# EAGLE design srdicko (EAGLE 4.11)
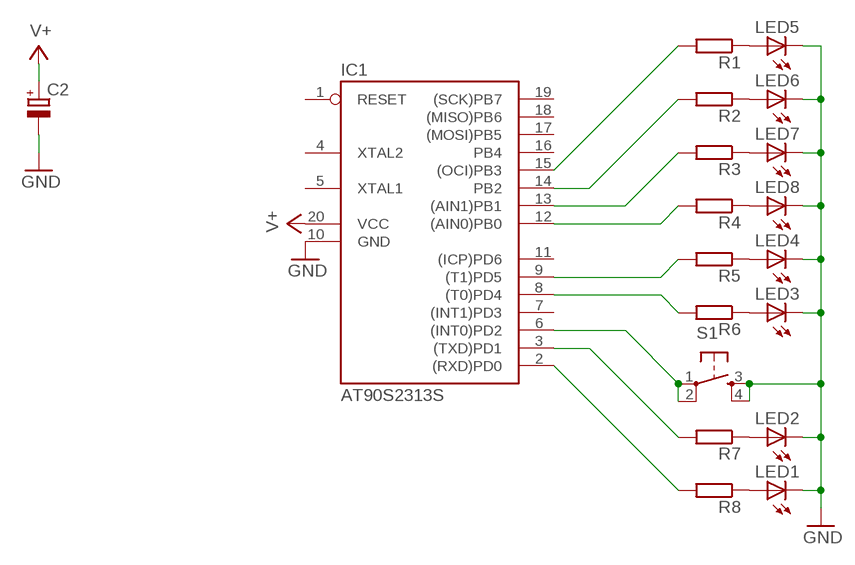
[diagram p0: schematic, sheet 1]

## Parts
C2  CPOL-EUE22-6AXIAL  [E22-6]
IC1  AT90S2313S  [SO20W]
LED1  LEDCHIPLED_1206  [CHIPLED_1206]
LED2  LEDCHIPLED_1206  [CHIPLED_1206]
LED3  LEDCHIPLED_1206  [CHIPLED_1206]
LED4  LEDCHIPLED_1206  [CHIPLED_1206]
LED5  LEDCHIPLED_1206  [CHIPLED_1206]
LED6  LEDCHIPLED_1206  [CHIPLED_1206]
LED7  LEDCHIPLED_1206  [CHIPLED_1206]
LED8  LEDCHIPLED_1206  [CHIPLED_1206]
R1  R-EU_M1206  [M1206]
R2  R-EU_M1206  [M1206]
R3  R-EU_M1206  [M1206]
R4  R-EU_M1206  [M1206]
R5  R-EU_M1206  [M1206]
R6  R-EU_M1206  [M1206]
R7  R-EU_M1206  [M1206]
R8  R-EU_M1206  [M1206]
S1  TAC_SWITCHSND  [TACTILE_SWITCH_SMD]

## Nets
N$1: LED5.A R1.1
N$2: LED6.A R2.1
N$3: LED7.A R3.1
N$4: LED8.A R4.1
N$5: LED4.A R5.1
N$6: LED3.A R6.1
N$7: LED2.A R7.1
N$8: IC1.3((TXD)PD1) R7.2
N$9: LED1.A R8.1
N$10: IC1.2((RXD)PD0) R8.2
N$11: IC1.8((T0)PD4) R6.2
N$12: IC1.9((T1)PD5) R5.2
N$13: IC1.12((AIN0)PB0) R4.2
N$14: IC1.13((AIN1)PB1) R3.2
N$15: IC1.14(PB2) R2.2
N$16: IC1.15((OCI)PB3) R1.2
N$17: IC1.6((INT0)PD2) S1.1 S1.2
N$19: C2.- IC1.10(GND) LED1.C LED2.C LED3.C LED4.C LED5.C LED6.C LED7.C LED8.C S1.3 S1.4 ; supply symbol labelled GND
V+: C2.+ IC1.20(VCC)
Unconnected: IC1.1(RESET) IC1.4(XTAL2) IC1.5(XTAL1) IC1.7((INT1)PD3) IC1.11((ICP)PD6) IC1.16(PB4) IC1.17((MOSI)PB5) IC1.18((MISO)PB6) IC1.19((SCK)PB7)

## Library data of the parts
C2 = rcl:CPOL-EU: POLARIZED CAPACITOR, European symbol
IC1 = atmel:AT90S2313: MICROCONTROLLER 2 Kbytes FLASH 128 bytes SRAM 128 bytes EEPROM UART
LED1-LED8 = led:LED: LED
R1-R8 = rcl:R-EU_: RESISTOR, European symbol
S1 = SparkFun:TAC_SWITCH: Momentary Switch Button commonly used for reset or general input. Spark Fun Electronics SKU : COM-00097

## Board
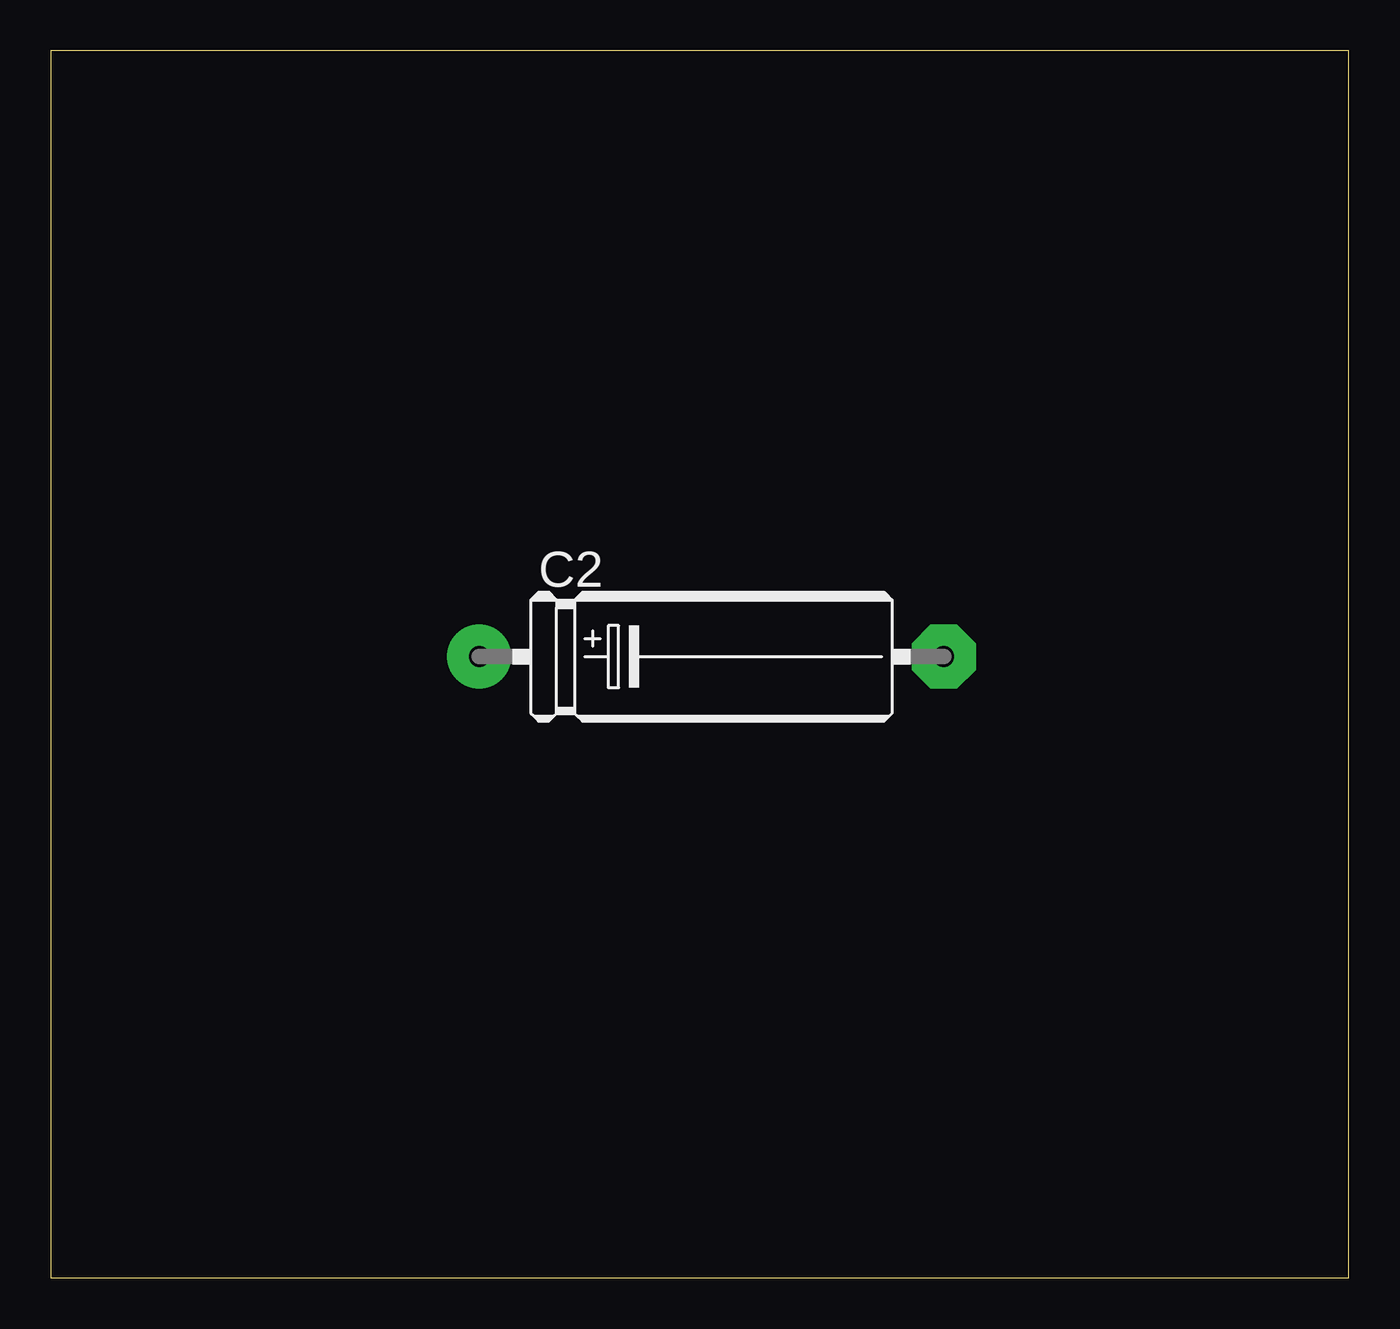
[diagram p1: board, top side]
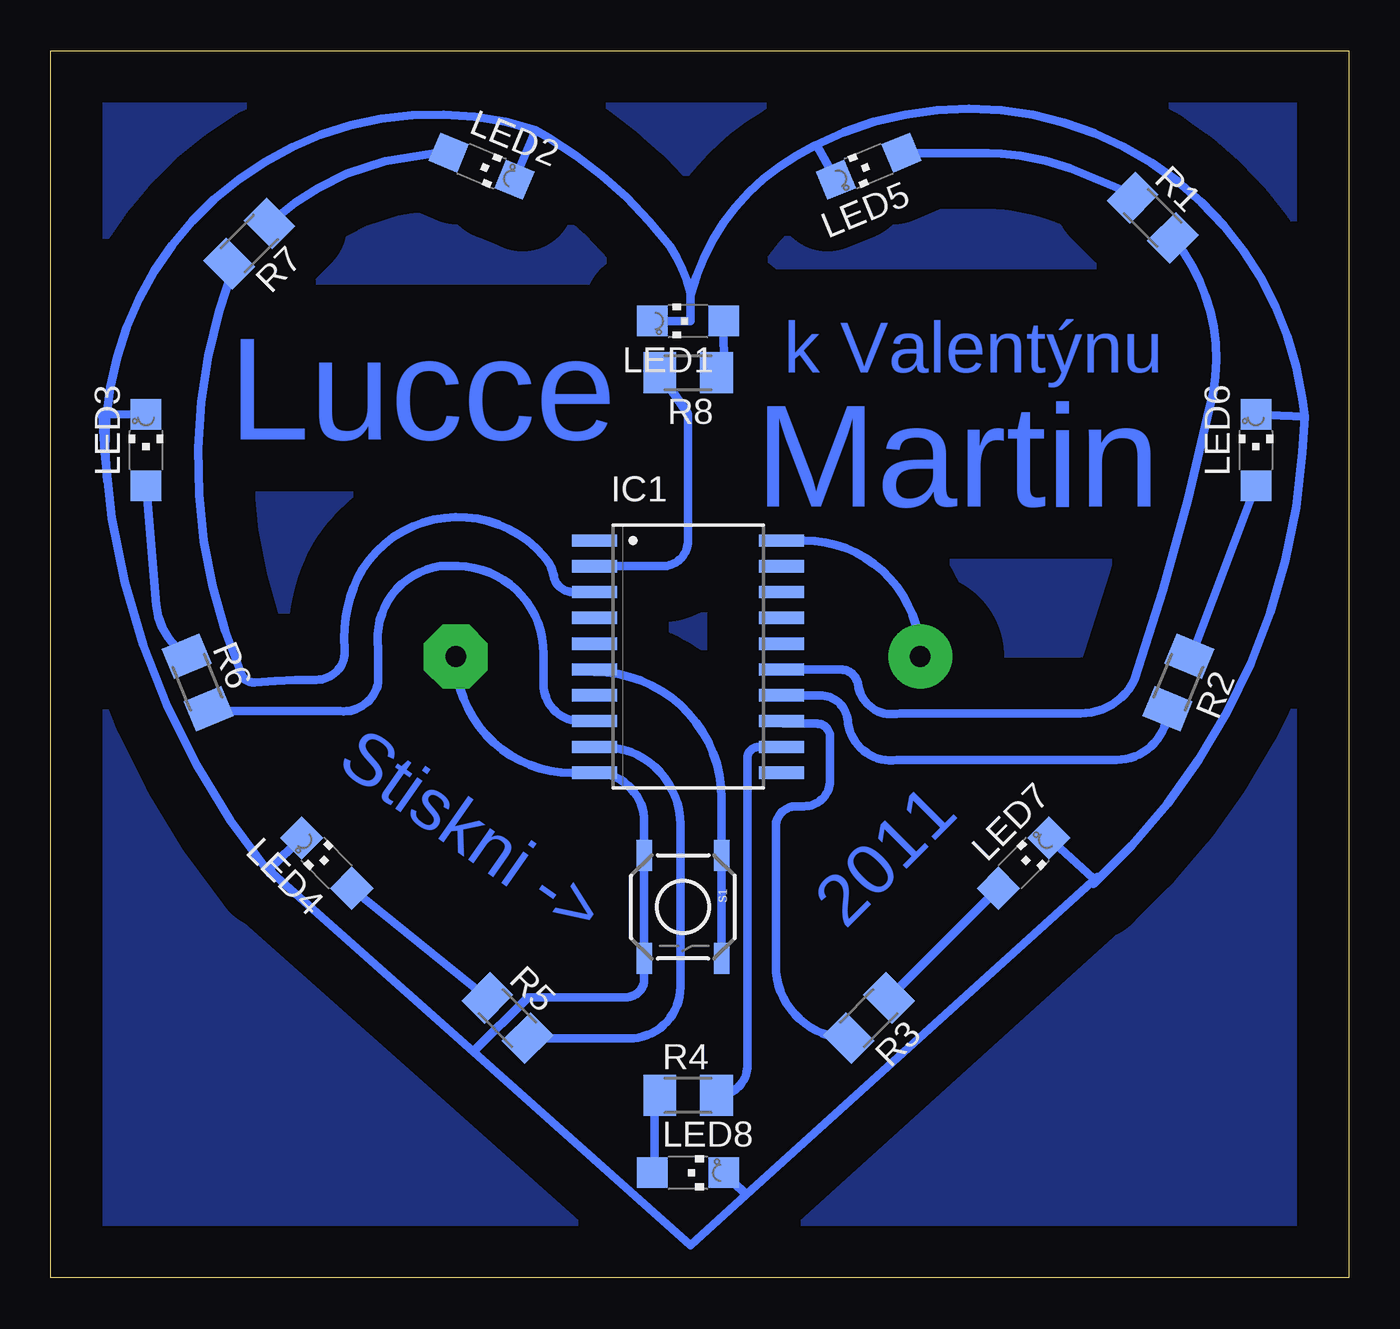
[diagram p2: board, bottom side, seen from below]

Size 63.86 x 60.38 mm. Coordinates in mm from the lower left corner, seen from the top.
Outline: 0,0 63.86,0 63.86,60.38 0,60.38 0,0
Copper layers (1*16): Top 0.035mm / dielectric 1.5mm / Bottom 0.035mm
Design rules "default": minimum track width 10mil, minimum drill 24mil, track to track 8mil, track to pad 8mil, pad to pad 8mil, via to via 8mil, smd to smd 8mil, copper to edge 40mil, drill to drill 8mil, minimum pad ring 10mil, minimum via ring 8mil, stop-mask expansion 4mil, vias tented up to drill 0mil, thermal gap 10mil

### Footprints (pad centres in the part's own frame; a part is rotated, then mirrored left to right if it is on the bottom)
E22-6 = drill 1.016 pad 3.15 round: + -11.43,0 | drill 1.016 pad 3.15 octagon: - 11.43,0
SO20W = smd 0.6 x 2.2: 1 -5.715,-4.6; 2 -4.445,-4.6; 3 -3.175,-4.6; 4 -1.905,-4.6; 5 -0.635,-4.6; 6 0.635,-4.6; 7 1.905,-4.6; 8 3.175,-4.6; 9 4.445,-4.6; 10 5.715,-4.6; 11 5.715,4.6; 12 4.445,4.6; 13 3.175,4.6; 14 1.905,4.6; 15 0.635,4.6; 16 -0.635,4.6; 17 -1.905,4.6; 18 -3.175,4.6; 19 -4.445,4.6; 20 -5.715,4.6
CHIPLED_1206 = smd 1.5 x 1.5: A 0,-1.75; C 0,1.75
M1206 = smd 1.6 x 2: 1 -1.4,0; 2 1.4,0
TACTILE_SWITCH_SMD = smd 1.524 x 0.762: 1 -2.54,1.905; 2 2.54,1.905; 3 -2.54,-1.905; 4 2.54,-1.905

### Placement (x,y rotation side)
C2  32.51,30.57 0 top
IC1  32.51,30.57 270 bottom
LED1  32.51,47.08 90 bottom
LED2  42.67,54.7 247.5 bottom
LED3  59.18,40.73 0 bottom
LED4  50.29,20.41 45 bottom
LED5  23.62,54.7 112.5 bottom
LED6  4.57,40.73 0 bottom
LED7  16,20.41 315 bottom
LED8  32.51,5.17 270 bottom
R1  9.65,52.16 315 bottom
R2  8.38,29.3 247.5 bottom
R3  23.62,12.79 225 bottom
R4  32.51,8.98 0 bottom
R5  41.4,12.79 315 bottom
R6  56.64,29.3 292.5 bottom
R7  54.1,50.89 225 bottom
R8  32.51,44.54 180 bottom
S1  32.76,18.25 270 bottom

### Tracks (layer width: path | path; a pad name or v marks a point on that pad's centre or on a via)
N$1
  Bottom 0.406: 22.04,55.33 22.22,55.33 | 22.04,55.33 LED5.A | R1.1 10.93,53.44 13.72,54.6 14.93,54.97 16.15,55.21 17.1,55.3 17.73,55.33 22.04,55.33
N$2
  Bottom 0.406: R2.1 7.74,30.57 LED6.A
N$3
  Bottom 0.406: R3.1 LED7.A
N$4
  Bottom 0.406: LED8.A 34.16,5.27 34.16,8.73 R4.1
N$5
  Bottom 0.406: R5.1 42.41,13.81 LED4.A
N$6
  Bottom 0.406: LED3.A 58.67,33.11 arc-50 57.27,30.7 R6.1
N$7
  Bottom 0.406: R7.1 51.83,52.9 50.7,53.63 49.31,54.33 47.4,54.95 44.49,55.4 LED2.A
N$8
  Bottom 0.406: IC1.3 38.1,33.74 arc83 39.11,34.51 arc-33 39.62,35.52 arc-106 48.51,34.89 arc-36 49.4,30.95 arc96 50.8,29.43 arc-5 53.84,29.3 arc72 54.48,29.68 arc44 54.86,49.75 R7.2
N$9
  Bottom 0.406: R8.1 30.73,44.54 LED1.A
N$10
  Bottom 0.406: R8.2 32.51,42.51 32.51,36.28 arc90 33.78,35.01 IC1.2
N$11
  Bottom 0.406: IC1.8 37.59,27.39 arc90 39.62,29.04 39.62,30.7 arc-90 43.81,35.01 44.7,35.01 arc-90 47.75,30.95 47.75,29.3 arc90 49.78,27.9 55.88,27.9 arc90 56,28.03 arc90 56.03,28 R6.2
N$12
  Bottom 0.406: IC1.9 36.7,26.12 arc90 32.89,22.31 32.89,14.31 arc90 35.43,11.77 40.51,11.77 arc90 40.48,11.8 R5.2
N$13
  Bottom 0.406: IC1.12 28.95,26.12 arc-90 29.59,25.62 29.59,10.5 arc90 30.98,8.98 R4.2
N$14
  Bottom 0.406: R3.2 arc90 28.19,15.38 28.19,22.19 arc90 27.17,23.2 26.79,23.2 arc-90 25.52,24.47 25.52,26.63 arc-90 26.16,27.27 27.81,27.27 27.81,27.29 arc-90 IC1.13
N$15
  Bottom 0.406: R2.2 arc90 11.43,25.49 22.22,25.49 arc90 24.63,27.27 arc-90 26.03,28.66 IC1.14
N$16
  Bottom 0.406: 20.82,27.77 20.7,27.77 | 20.82,27.77 22.09,27.77 arc90 24.12,29.04 arc-90 25.01,29.93 IC1.15 | 20.82,27.77 13.2,27.77 arc-64 10.54,29.43 arc-7 6.85,42.76 arc-55 8.63,51.14 | 8.63,51.14 8.76,51.02 | 8.5,51.14 8.76,50.89 8.63,51.14 | 8.63,51.14 8.76,50.76 | 8.63,51.14 R1.2
N$17
  Bottom 0.406: S1.2 S1.1 30.86,23.58 arc-90 37.08,29.81 arc90 37.11,29.83 IC1.6
N$18
  pour Bottom (isolate 2.54): -0.13,60.41 -0.13,-0.04 63.88,-0.04 63.75,60.41
N$19
  Bottom 0.406: C2.- arc-90 38.22,24.85 IC1.10 37.08,24.85 arc90 34.67,22.44 S1.3 S1.4 34.67,14.69 arc90 35.55,13.81 40.38,13.81 43.05,11.14 43.05,11.13 43.07,11.11 | 53,19.96 52.95,19.9 43.07,11.11 | 53,19.96 53.12,20.12 53.08,20.15 LED4.C | 43.07,11.11 32.38,1.61 29.65,4.08 | 12.64,19.47 12.51,19.58 | 12.64,19.47 29.65,4.08 | 12.51,19.58 arc-6 12.38,19.72 | 32.38,48.35 32.38,48.48 arc-17 33.4,50.76 arc-22 39.37,56.1 40,56.48 | 32.38,48.35 32.38,47.08 LED1.C 34.29,47.08 | 2.15,42.38 LED6.C | 12.51,19.58 12.57,19.65 LED7.C | 29.65,4.08 29.71,4.15 LED8.C | 61.34,42.51 LED3.C | 2.15,42.38 2.28,40.6 arc44 12.57,19.39 12.64,19.47 | 61.34,42.51 61.21,40.6 arc-35 53.08,19.9 53,19.96 | LED5.C 26.16,55.71 26.28,55.71 | 40,56.48 LED2.C | 61.34,42.51 61.08,39.2 arc114 40,56.48 | 2.15,42.38 2.28,43.27 arc-109 26.28,55.71 | 26.28,55.71 27.17,55.21 arc-46 32.38,48.35
V+
  Bottom 0.406: IC1.20 26.79,36.28 arc90 C2.+

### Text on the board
Bottom: k Valentýnu | Lucce | Martin | Stiskni -> | 2011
